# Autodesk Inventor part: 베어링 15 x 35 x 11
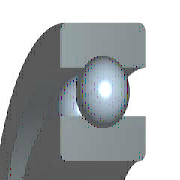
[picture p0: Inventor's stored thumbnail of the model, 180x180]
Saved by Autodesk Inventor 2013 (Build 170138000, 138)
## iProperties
Created: 2012-02
Part Number: 베어링 15 x 35 x 11
Material: 강철, 연강
Description: 깊은 그루브 볼 베어링
Document SubType Name: Modeling
Standard: KS B 2023
Designer: mduedu
Standards Organization: KS
Language: ko-KR
Size Designation: 6202 - 15 x 35 x 11
Categories: <MemberInstance><Categories><Category DisplayName="샤프트 부품" InternalName="7f7aeb1f-a693-4053-b835-cee3144e0d98" Mnemonic="SHFT"><Category DisplayName="베어링" Inter
Density: 1 g/cm^3
IsCustomPart: 1
Author: mduedu
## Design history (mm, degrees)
sketch "스케치" dims "d0" = 5.2 (= -0.26 x WD + 0.26 x BD)
  geometry: L1 (2.9, 12.5)-(8.1, 12.5); L2 (5.5, 12.5)-(5.5, 9.9); L3 (5.5, 12.5)-(5.5, 15.1); L4 (3.568, 10.76)-(0, 10.76); L5 (0, 7.5)-(11, 7.5); L6 (3.568, 14.24)-(0, 14.24); L7 (0, 17.5)-(11, 17.5); L8 (11, 7.5)-(11, 10.76); L9 (7.432, 10.76)-(11, 10.76); L10 (7.432, 14.24)-(11, 14.24); L11 (11, 17.5)-(11, 14.24); L12 (-1.4, 0)-(8.4, 0) reference; L13 (0, -0.3)-(0, 5.3) reference
  constraints: 22 end point, 4 point on line, 2 collinear, 2 perpendicular, 2 symmetric about line, 1 midpoint, 1 parallel, 14 other
  dimensions: "d9" = 15 diameter of L5 L12 (= WD); "d11" = 35 diameter of L7 L12 (= BD); "d12" = 11 distance between parallel lines of L8 L13 (= KB); "d13" = 21.52 diameter of L9 L12 (= 0.326 x BD + 0.674 x WD)
revolve "본체" stored, may be unused: angle "d6" = 90 deg
revolve "볼" stored, may be unused: angle "d7" = 90 deg
pattern_circular "IDS_ARRAYBALL[SIMPL:T]" dims angle "d3" = 360 deg
body "Solid1"
fillet "모깎기1" dims "d1" = 0.6 (= KRS)
other parameters: "WD" = 15 [user parameter; used in 5 equation terms], "BD" = 35 [user parameter; used in 5 equation terms], "KB" = 11 [user parameter; used in 1 equation term], "KRS" = 0.6 [user parameter; used in 1 equation term], "d4" = 0, "d5" = 0, "d8" = 0, "d14" = 0, "d15" = 0, "BBA" = 0 [user parameter], "BC0" = 3750000 [user parameter], "BC" = 7800000 [user parameter], "BR" = 17.5 (= 0.5 x BD) [user parameter], "WR" = 7.5 (= 0.5 x WD) [user parameter]
